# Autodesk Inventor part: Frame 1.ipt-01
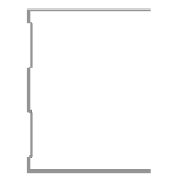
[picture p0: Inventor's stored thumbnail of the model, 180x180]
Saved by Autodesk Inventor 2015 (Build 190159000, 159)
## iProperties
Created: 2015-04
Part Number: Frame 1.ipt-01
Material: Aluminum 6061
Document SubType Name: Modeling
Standard: Unnamed
Designer: suporte
Language: en-US
Size Designation: (Unnamed 1)
Categories: <MemberInstance><Categories><Category DisplayName="Structural Shapes" InternalName="089c4875-fa83-4c05-b084-43b9cc11f5ed" Mnemonic="GRDR"><CategoryParameter Dis
Density: 2.7 g/cm^3
Appearance: Aluminum - Flat
IsCustomPart: 1
_CCFamilyMember: 1
_CCFamilyDisplayName: Frame 1
_FrameMemberDoc: Frame Member File
_Version: 15.0.0
_GetPNFromCC: 1
G_L: 742,325 mm
G_W: 70,000 mm
G_H: 75,000 mm
+5C76CBEB-8B41-4733-85A3-2AE3D2FC03BA+CUTDETAIL1: Miter 67,51 deg
+1278F890-8875-45A9-BBA4-B9D5376CE797+CUTDETAIL2: Cut
Author: suporte
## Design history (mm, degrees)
node "Start Plane"
node "End Plane"
sketch "Sketch"
  geometry: L1 (34.6, 37.5)-(34.6, 36.7); L2 (34.6, 36.7)-(-34.6, 36.7); L3 (-34.6, -36.7)-(34.6, -36.7); L4 (34.6, -36.7)-(34.6, -37.5); L5 (34.6, -37.5)-(-35.4, -37.5); L6 (-35.4, 37.5)-(34.6, 37.5); L7 (-34.6, 36.7)-(-34.6, 31.7); L8 (-34.6, 31.7)-(-33.4, 30.5); L9 (-33.4, 30.5)-(-33.4, 10.746); L10 (-33.4, 10.746)-(-34.6, 9.546); L11 (-34.6, 9.546)-(-34.6, -9.546); L12 (-34.6, -9.546)-(-33.4, -10.746); L13 (-33.4, -10.746)-(-33.4, -30.5); L14 (-33.4, -30.5)-(-34.6, -31.7); L15 (-34.6, -31.7)-(-34.6, -36.7); L16 (-35.4, -37.5)-(-35.4, -31.369); L17 (-35.4, -31.369)-(-34.2, -30.169); L18 (-34.2, -30.169)-(-34.2, -11.077); L19 (-34.2, -11.077)-(-35.4, -9.877); L20 (-35.4, -9.877)-(-35.4, 9.877); L21 (-35.4, 9.877)-(-34.2, 11.077); L22 (-34.2, 11.077)-(-34.2, 30.169); L23 (-34.2, 30.169)-(-35.4, 31.369); L24 (-35.4, 31.369)-(-35.4, 37.5); L25 (-35.4, 0)-(30.37, 0); 3 further points
  constraints: 50 end point, 10 point on line, 9 parallel, 5 perpendicular, 4 equal length, 3 midpoint, 3 vertical, 2 vertical alignment, 1 collinear, 1 horizontal, 1 horizontal alignment
  dimensions: "d3" = 0.8 distance of L1.start L1.end; "d5" = 75 distance between parallel lines of L5 L6; "d6" = 0.8 distance between parallel lines of L24 L7; "d7" = 0.8 distance between parallel lines of L8 L23; "d8" = 0.8 distance between parallel lines of L22 L9; "d9" = 0.8 distance between parallel lines of L17 L14; "d10" = 0.8 distance between parallel lines of L13 L18; "d11" = 0.8 distance between parallel lines of L12 L19; "d12" = 0.8 distance between parallel lines of L21 L10; "d13" = 5 distance of L2.end L7.end; "d15" = 135 deg angle of L9 L8; "d16" = 2 distance between parallel lines of L24 L9; "d17" = 70 distance of L6.start L1.start
extrude "Body" join sketch "Sketch" stored distance "d24" = 0.13; taper "d25" = 0 deg
node "Driven Length"
  sketch "Sketch8"
    geometry: L1 (0, 0)-(10, 0) reference
    constraints: 2 end point, 1 horizontal
  workplane "Work Plane6"
  sketch "Sketch9"
    geometry: L1 (-2, -36.226)-(12, -36.226) reference; L2 (-2, 706.099)-(12, 706.099) reference
    dimensions: "d27" = 742.32488 distance between parallel lines of L1 L2 (derived)
workplane "Work Plane7"
split "Split1"
workplane "Work Plane8"
split "Split2"
body "Solid1"
other parameters: "tamanho" = 718.59902, "G_OFFSET_START" = 36.22585 [user parameter; used in 1 equation term], "G_OFFSET_END" = -12.5 [user parameter; used in 1 equation term], "d22" = -36.22585 (= -G_OFFSET_START), "d23" = 706.09902 (= tamanho + G_OFFSET_END), "G_L" = 742.32488 (= d27) [user parameter], "d32" = 90 deg
